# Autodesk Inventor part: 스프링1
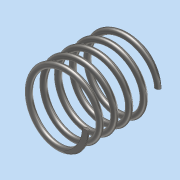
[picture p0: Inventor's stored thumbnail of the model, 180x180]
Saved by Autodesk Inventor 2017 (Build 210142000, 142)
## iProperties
Part Number: 스프링1
Material: 강철, 연강
Document SubType Name: Modeling
Designer: MRC
Density: 7.85 g/cm^3
Appearance: 반연마
Mass: 8.42324 g
Surface Area: 21.7217 cm^2
Volume: 1.07302 cm^3
Author: MRC
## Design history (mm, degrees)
sketch "스케치1"
  geometry: L1 (0, 0)-(0, 25.358); L2 (0, 25.358)-(11, 25.358); L3 (0, 0)-(11, 0); C1 r 1 at (11, 0)
  constraints: 6 end point, 2 horizontal, 1 centre point, 1 coincident, 1 vertical
  dimensions: "d0" = 25.35829 distance of L1.start L1.end (derived); "d2" = 22 diameter of L3.end L1; "d3" = 2 diameter of C1; "d4" = 22 diameter of L2.end L1
feature "코일1" pitch "d5" = 10; turns "d7" = 5; dims "d6" = 25.35829 (= d0), "d8" = 0, angle "d9" = 90 deg, angle "d10" = 90 deg, "d11" = 0, "d12" = 0
sketch "스케치2"
  geometry: L1 (-13.313, 0)-(15.035, 0); L2 (15.035, 0)-(15.035, 25.358); L3 (15.035, 25.358)-(-13.313, 25.358); L4 (-13.313, 25.358)-(-13.313, 0); 1 further point
  constraints: 8 end point, 2 parallel, 1 horizontal, 1 perpendicular
  dimensions: "d13" = 25.35829 distance of L1.end L2.end (= d0)
extrude "돌출1" sketch "스케치2" stored distance "d14" = 0; taper "d15" = 0 deg
node "솔리드1"
